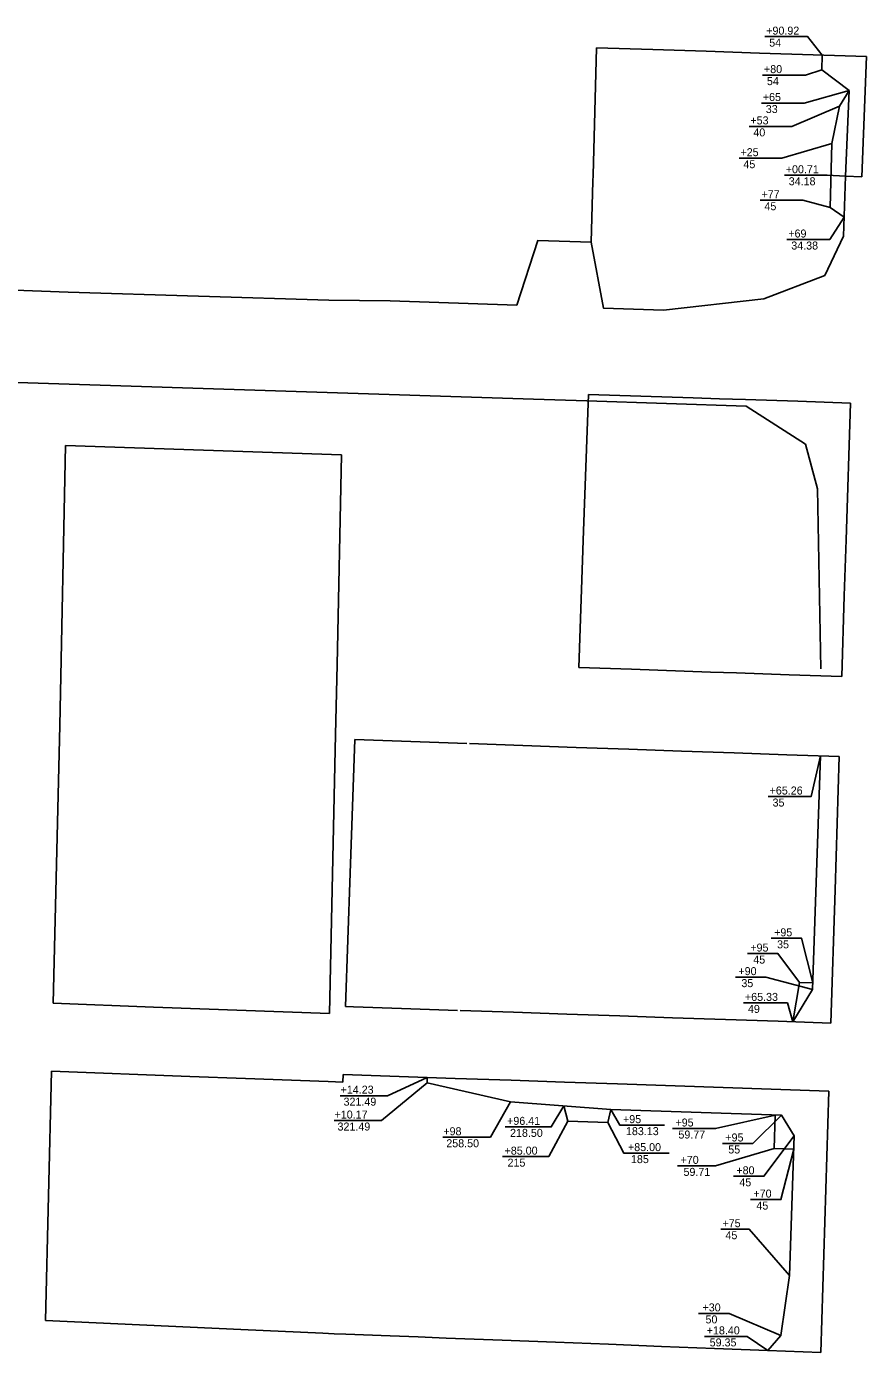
# Model space of a CAD drawing. Extents: x 979729 to 993523, y 1834148 to 1845433.
# Drawn here: x 991875 to 992504, y 1843173 to 1844167 of the extents above; entities that cross this region are included whole.
import ezdxf

# ---------------------------------------------------------------- set-up
doc = ezdxf.new("R2010")
doc.units = 0
for name, color, linetype in [('51', 7, 'Continuous'), ('53', 7, 'Continuous'), ('R_Draft', 7, 'Continuous'), ('S_EXIST_ROW', 7, 'Continuous')]:
    doc.layers.add(name, color=color, linetype=linetype)

msp = doc.modelspace()

# ---------------------------------------------------------------- linework, layer by layer
at = {"layer": '51'}
for p, q in [((992470.87, 1844134.6), (992471.17, 1844145.52)), ((992491.46, 1844119.04), (992470.87, 1844134.6)), ((992488.54, 1844054.81), (992491.46, 1844119.04)), ((992440, 1843185.53), (992446.54, 1843230.33)), ((992446.54, 1843230.33), (992446.54, 1843230.33)), ((992446.54, 1843230.33), (992446.54, 1843230.33)), ((992430.25, 1843174.25), (992440, 1843185.53)), ((992440, 1843185.53), (992440, 1843185.53))]:
    msp.add_line(p, q, dxfattribs=at)
for points in [[(992449.06, 1843420.68), (992463.9, 1843444.86), (992469.91, 1843620.02)], [(992446.54, 1843230.33), (992450.14, 1843335.27), (992440.66, 1843350.6), (992312.61, 1843354.99), (992237.38, 1843360.58), (992174.84, 1843374.89), (992174.98, 1843378.95)]]:
    msp.add_lwpolyline(points, dxfattribs=at)
at = {"layer": '53'}
for p, q in [((992277.3, 1843357.61), (992280.41, 1843346.09)), ((992312.61, 1843354.99), (992310.39, 1843345.06)), ((992310.39, 1843345.06), (992280.41, 1843346.09))]:
    msp.add_line(p, q, dxfattribs=at)
for points in [[(992487.49, 1844024.06), (992477.08, 1844031.4), (992478.38, 1844079.38), (992484.13, 1844107.24), (992491.46, 1844119.04)], [(992449.06, 1843420.68), (992454.08, 1843450.2), (992464.07, 1843449.86)], [(992449.79, 1843325.28), (992435.09, 1843325.78), (992435.88, 1843350.77)]]:
    msp.add_lwpolyline(points, dxfattribs=at)
at = {"layer": 'R_Draft'}
for p, q in [((992428.17, 1844159.41), (992454.24, 1844159.41)), ((992426.48, 1844130.56), (992452.55, 1844130.56)), ((992425.6, 1844109.62), (992451.68, 1844109.62)), ((992416.29, 1844092.1), (992442.37, 1844092.1)), ((992408.84, 1844068.26), (992434.92, 1844068.26)), ((992442.81, 1844055.47), (992468.89, 1844055.47)), ((992424.61, 1844036.76), (992450.68, 1844036.76)), ((992444.72, 1844007.27), (992470.79, 1844007.27)), ((992430.71, 1843589.6), (992456.78, 1843589.6)), ((992432.91, 1843483.28), (992449.73, 1843483.28)), ((992415.06, 1843471.84), (992431.88, 1843471.84)), ((992406.13, 1843454.18), (992422.96, 1843454.18)), ((992412.25, 1843434.84), (992439.08, 1843434.84)), ((992109.62, 1843365.29), (992139.29, 1843365.29)), ((992105.1, 1843346.64), (992134.78, 1843346.64)), ((992233.41, 1843341.89), (992262.02, 1843341.89)), ((992325.4, 1843343.2), (992352.92, 1843343.2)), ((992358.93, 1843340.65), (992385.17, 1843340.65)), ((992186.66, 1843334.11), (992216.33, 1843334.11)), ((992396.31, 1843329.45), (992413.13, 1843329.45)), ((992231.53, 1843319.58), (992260.13, 1843319.58)), ((992328.35, 1843322.22), (992356.45, 1843322.22)), ((992362.74, 1843312.65), (992385.17, 1843312.65)), ((992404.62, 1843304.83), (992421.44, 1843304.83)), ((992417.39, 1843287.37), (992434.21, 1843287.37)), ((992395.15, 1843265.15), (992410.42, 1843265.15)), ((992378.43, 1843202.02), (992395.44, 1843202.02)), ((992382.77, 1843184.78), (992408.82, 1843184.78))]:
    msp.add_line(p, q, dxfattribs=at)
for points in [[(992471.17, 1844145.52), (992460.24, 1844159.41), (992454.24, 1844159.41)], [(992470.87, 1844134.6), (992458.55, 1844130.56), (992452.55, 1844130.56)], [(992491.46, 1844119.04), (992457.68, 1844109.62), (992451.68, 1844109.62)], [(992484.13, 1844107.24), (992448.37, 1844092.1), (992442.37, 1844092.1)], [(992478.38, 1844079.38), (992440.92, 1844068.26), (992434.92, 1844068.26)], [(992488.54, 1844054.81), (992474.89, 1844055.47), (992468.89, 1844055.47)], [(992477.08, 1844031.4), (992456.68, 1844036.76), (992450.68, 1844036.76)], [(992487.49, 1844024.06), (992476.79, 1844007.27), (992470.79, 1844007.27)], [(992469.91, 1843620.02), (992462.78, 1843589.6), (992456.78, 1843589.6)], [(992464.07, 1843449.86), (992455.73, 1843483.28), (992449.73, 1843483.28)], [(992454.08, 1843450.2), (992437.88, 1843471.84), (992431.88, 1843471.84)], [(992463.9, 1843444.86), (992428.96, 1843454.18), (992422.96, 1843454.18)], [(992449.06, 1843420.68), (992445.08, 1843434.84), (992439.08, 1843434.84)], [(992174.84, 1843374.89), (992140.78, 1843346.64), (992134.78, 1843346.64)], [(992174.98, 1843378.95), (992145.29, 1843365.29), (992139.29, 1843365.29)], [(992237.38, 1843360.58), (992222.33, 1843334.11), (992216.33, 1843334.11)], [(992277.3, 1843357.61), (992268.02, 1843341.89), (992262.02, 1843341.89)], [(992312.61, 1843354.99), (992319.4, 1843343.2), (992325.4, 1843343.2)], [(992280.41, 1843346.09), (992266.13, 1843319.58), (992260.13, 1843319.58)], [(992310.39, 1843345.06), (992322.35, 1843322.22), (992328.35, 1843322.22)], [(992435.88, 1843350.77), (992391.17, 1843340.65), (992385.17, 1843340.65)], [(992440.66, 1843350.6), (992419.13, 1843329.45), (992413.13, 1843329.45)], [(992450.14, 1843335.27), (992427.44, 1843304.83), (992421.44, 1843304.83)], [(992435.09, 1843325.78), (992391.17, 1843312.65), (992385.17, 1843312.65)], [(992449.79, 1843325.28), (992440.21, 1843287.37), (992434.21, 1843287.37)], [(992446.54, 1843230.33), (992416.42, 1843265.15), (992410.42, 1843265.15)], [(992440, 1843185.53), (992401.44, 1843202.02), (992395.44, 1843202.02)], [(992430.25, 1843174.25), (992414.82, 1843184.78), (992408.82, 1843184.78)]]:
    msp.add_lwpolyline(points, dxfattribs=at)
at = {"layer": 'S_EXIST_ROW'}
for p, q in [((992299.35, 1844055.65), (992302.01, 1844151.13)), ((992302.01, 1844151.13), (992344.07, 1844149.73)), ((992344.07, 1844149.73), (992384.14, 1844148.41)), ((992384.14, 1844148.41), (992404.17, 1844147.74)), ((992404.17, 1844147.74), (992424.2, 1844147.08)), ((992424.2, 1844147.08), (992464.27, 1844145.75)), ((992464.27, 1844145.75), (992504.34, 1844144.42)), ((992504.34, 1844144.42), (992500.73, 1844054.4)), ((992297.96, 1844005.25), (992299.23, 1844051.12)), ((992299.23, 1844051.12), (992299.35, 1844055.65)), ((992292.29, 1843788.77), (992295.84, 1843891.11)), ((992335.12, 1843889.82), (992295.84, 1843891.11)), ((992254.75, 1843887.65), (992294.73, 1843886.29)), ((992374.4, 1843888.54), (992335.12, 1843889.82)), ((992394.04, 1843887.89), (992374.4, 1843888.54)), ((992413.68, 1843887.25), (992394.04, 1843887.89)), ((992452.96, 1843885.97), (992413.68, 1843887.25)), ((992492.24, 1843884.68), (992452.96, 1843885.97)), ((992489.04, 1843782.06), (992492.24, 1843884.68)), ((991899.57, 1843642.88), (991903.87, 1843852.72)), ((992110.73, 1843845.92), (991903.87, 1843852.72)), ((992107.36, 1843688.33), (992110.73, 1843845.92)), ((992288.73, 1843686.44), (992292.29, 1843788.77)), ((992487.73, 1843740.08), (992489.04, 1843782.06)), ((992487.73, 1843740.08), (992485.84, 1843679.49)), ((992106.25, 1843636.09), (992107.36, 1843688.33)), ((992328.15, 1843685.05), (992288.73, 1843686.44)), ((992367.57, 1843683.66), (992328.15, 1843685.05)), ((992387.28, 1843682.97), (992367.57, 1843683.66)), ((992406.99, 1843682.27), (992387.28, 1843682.97)), ((992446.42, 1843680.88), (992406.99, 1843682.27)), ((992485.84, 1843679.49), (992446.42, 1843680.88)), ((991894.66, 1843434.55), (991899.57, 1843642.88)), ((992101.78, 1843426.89), (992106.25, 1843636.09)), ((992120.75, 1843632.32), (992117.27, 1843532.19)), ((992162.72, 1843630.84), (992120.75, 1843632.32)), ((992204.7, 1843629.36), (992162.72, 1843630.84)), ((992246.67, 1843627.88), (992206.7, 1843629.29)), ((992286.65, 1843626.47), (992246.67, 1843627.88)), ((992326.11, 1843625.08), (992286.65, 1843626.47)), ((992365.57, 1843623.69), (992326.11, 1843625.08)), ((992405.04, 1843622.3), (992365.57, 1843623.69)), ((992405.04, 1843622.3), (992444.5, 1843620.91)), ((992444.5, 1843620.91), (992483.97, 1843619.52)), ((992483.97, 1843619.52), (992480.85, 1843519.62)), ((992117.27, 1843532.19), (992113.79, 1843432.06)), ((992480.85, 1843519.62), (992477.73, 1843419.71)), ((991969.8, 1843431.77), (991894.66, 1843434.55)), ((992101.78, 1843426.89), (991969.8, 1843431.77)), ((992113.79, 1843432.06), (992119.79, 1843431.86)), ((992119.79, 1843431.86), (992155.77, 1843430.64)), ((992197.74, 1843429.21), (992155.77, 1843430.64)), ((992199.74, 1843429.14), (992239.72, 1843427.79)), ((992239.72, 1843427.79), (992279.69, 1843426.43)), ((992279.69, 1843426.43), (992319.3, 1843425.09)), ((992358.91, 1843423.74), (992319.3, 1843425.09)), ((992398.52, 1843422.4), (992358.91, 1843423.74)), ((992438.13, 1843421.05), (992398.52, 1843422.4)), ((992477.73, 1843419.71), (992438.13, 1843421.05)), ((991891.07, 1843290.07), (991893.39, 1843383.56)), ((991997.04, 1843379.73), (991893.39, 1843383.56)), ((992038.76, 1843378.19), (991997.04, 1843379.73)), ((992100.69, 1843375.9), (992038.76, 1843378.19)), ((992111.83, 1843375.51), (992100.69, 1843375.9)), ((992112.02, 1843381.09), (992111.83, 1843375.51)), ((992154, 1843379.67), (992112.02, 1843381.09)), ((992195.97, 1843378.24), (992154, 1843379.67)), ((992237.95, 1843376.82), (992195.97, 1843378.24)), ((992277.92, 1843375.46), (992237.95, 1843376.82)), ((992277.92, 1843375.46), (992317.57, 1843374.12)), ((992317.57, 1843374.12), (992476.14, 1843368.73)), ((992473.09, 1843270.73), (992476.14, 1843368.73)), ((991888.75, 1843196.59), (991891.07, 1843290.07)), ((992470.03, 1843172.72), (992473.09, 1843270.73)), ((992035.17, 1843189.95), (991888.75, 1843196.59)), ((992096.66, 1843187.16), (992035.17, 1843189.95)), ((992105.27, 1843186.77), (992096.66, 1843187.16)), ((992114.09, 1843186.43), (992105.27, 1843186.77)), ((992147.24, 1843185.15), (992114.09, 1843186.43)), ((992168.22, 1843184.34), (992147.24, 1843185.15)), ((992189.21, 1843183.54), (992168.22, 1843184.34)), ((992231.17, 1843181.92), (992189.21, 1843183.54)), ((992271.14, 1843180.38), (992231.17, 1843181.92)), ((992271.14, 1843180.38), (992310.92, 1843178.85)), ((992310.92, 1843178.85), (992350.7, 1843177.32)), ((992350.7, 1843177.32), (992390.48, 1843175.78)), ((992390.48, 1843175.78), (992430.25, 1843174.25)), ((992430.25, 1843174.25), (992470.03, 1843172.72))]:
    msp.add_line(p, q, dxfattribs=at)
for points in [[(991312.19, 1844018.7), (991328.62, 1844018.14), (991352.63, 1843988.31), (991662.41, 1843976.79), (991712.39, 1843975.1), (991905.7, 1843967.89), (992101.2, 1843961.9), (992147.17, 1843961.34), (992242.11, 1843958.12), (992257.98, 1844006.61), (992297.96, 1844005.25), (992307.08, 1843955.91), (992352.05, 1843954.38), (992427.38, 1843962.83), (992473, 1843980.3), (992487.01, 1844009.84), (992488.54, 1844054.81), (992500.73, 1844054.4)], [(991307.74, 1843890.78), (991319.29, 1843890.39), (991340.22, 1843917.69), (991665.04, 1843906.67), (991705.01, 1843905.31), (992254.75, 1843887.65)], [(992294.73, 1843886.29), (992414.19, 1843882.23)], [(992414.19, 1843882.23), (992458.7, 1843853.71), (992467.57, 1843820.39), (992469.99, 1843685.3)]]:
    msp.add_lwpolyline(points, dxfattribs=at)

# ---------------------------------------------------------------- texts
at = {"layer": 'R_Draft'}
for s, p in [('+90.92', (992429.17, 1844160.91)), (' 54', (992429.17, 1844151.91)), ('+80', (992427.48, 1844132.06)), (' 54', (992427.48, 1844123.06)), ('+65', (992426.61, 1844111.12)), (' 33', (992426.61, 1844102.12)), ('+53', (992417.3, 1844093.6)), (' 40', (992417.3, 1844084.6)), ('+25', (992409.85, 1844069.76)), (' 45', (992409.85, 1844060.76)), ('+00.71', (992443.82, 1844056.97)), (' 34.18', (992443.82, 1844047.97)), ('+77', (992425.61, 1844038.26)), (' 45', (992425.61, 1844029.26)), ('+69', (992445.73, 1844008.77)), (' 34.38', (992445.73, 1843999.77)), ('+65.26', (992431.71, 1843591.1)), (' 35', (992431.71, 1843582.1)), ('+95', (992435.09, 1843484.78)), ('+95', (992417.24, 1843473.34)), (' 35', (992435.09, 1843475.78)), (' 45', (992417.24, 1843464.34)), ('+90', (992408.32, 1843455.68)), (' 35', (992408.32, 1843446.68)), ('+65.33', (992413.22, 1843436.34)), (' 49', (992413.22, 1843427.34)), ('+14.23', (992110.03, 1843366.79)), ('+10.17', (992105.51, 1843348.14)), (' 321.49', (992110.03, 1843357.79)), (' 321.49', (992105.51, 1843339.14)), ('+96.41', (992234.87, 1843343.39)), ('+95', (992321.77, 1843344.7)), ('+95', (992361.11, 1843342.15)), ('+98', (992187.07, 1843335.61)), (' 218.50', (992234.87, 1843334.39)), (' 183.13', (992321.77, 1843335.7)), (' 59.77', (992361.11, 1843333.15)), ('+95', (992398.49, 1843330.95)), (' 258.50', (992187.07, 1843326.61)), ('+85.00', (992232.99, 1843321.08)), ('+85.00', (992325.52, 1843323.72)), (' 55', (992398.49, 1843321.95)), (' 215', (992232.99, 1843312.08)), (' 185', (992325.52, 1843314.72)), ('+70', (992364.92, 1843314.15)), (' 59.71', (992364.92, 1843305.15)), ('+80', (992406.8, 1843306.33)), (' 45', (992406.8, 1843297.33)), ('+70', (992419.57, 1843288.87)), (' 45', (992419.57, 1843279.87)), ('+75', (992396.37, 1843266.65)), (' 45', (992396.37, 1843257.65)), ('+30', (992381.4, 1843203.52)), (' 50', (992381.4, 1843194.52)), ('+18.40', (992384.55, 1843186.28)), (' 59.35', (992384.55, 1843177.28))]:
    msp.add_text(s, height=6, rotation=360, dxfattribs=at).set_placement(p)

doc.saveas('drawing.dxf')
